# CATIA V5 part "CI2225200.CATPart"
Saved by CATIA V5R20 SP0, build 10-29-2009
Part number: CI2225200
Bounding box of the stored display mesh (mm): x -24 to 24, y -18.534 to 234.5, z -34.099 to 26.514
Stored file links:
  C:\Users\Raffaele\Desktop\3D X SITO CF\BOLEX\19-INCLINED ASSEMBLY REF_CI\CI2225200.CATPart
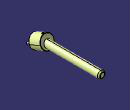
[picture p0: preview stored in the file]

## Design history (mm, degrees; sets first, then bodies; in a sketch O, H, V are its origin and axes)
Set1
  DatumSurface1 to DatumSurface16 "MANIFOLD_SOLID_BREP #393"
  DatumSurface17 to DatumSurface39 "MANIFOLD_SOLID_BREP #1138"
Body1 (main body)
